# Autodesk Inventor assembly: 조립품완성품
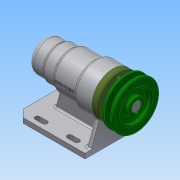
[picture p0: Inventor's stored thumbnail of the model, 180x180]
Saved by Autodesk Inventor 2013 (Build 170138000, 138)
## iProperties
Created: 2017-09
Part Number: 조립품완성품
Document SubType Name: Assembly
Designer: Administrator
Author: Administrator
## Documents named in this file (12)
- C:\Users\Administrator\Desktop\470908V1006\조립품완성품.iam
- C:\Users\Administrator\Desktop\470908V1006\부품완성품.ipt
- C:\Users\Administrator\Desktop\470908V1006\커버.ipt
- C:\Users\Administrator\Desktop\470908V1006\오일 실 20x35x7.ipt
- C:\Users\Administrator\Desktop\470908V1006\베어링 6004.ipt
- C:\Users\Administrator\Desktop\470908V1006\축.ipt
- C:\Users\Administrator\Desktop\470908V1006\어댑터슬리브.ipt
- C:\Users\Administrator\Desktop\470908V1006\베어링 51202.ipt
- C:\Users\Administrator\Desktop\470908V1006\볼트 M4 x 12.ipt
- C:\Users\Administrator\Desktop\470908V1006\키 5 x 5 x 16.ipt
- C:\Users\Administrator\Desktop\470908V1006\멈춤나사 M3x8.ipt
- C:\Users\Administrator\Desktop\470908V1006\V벨트풀리.ipt
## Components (1 placed, 1 different names)
1. V벨트풀리:1
